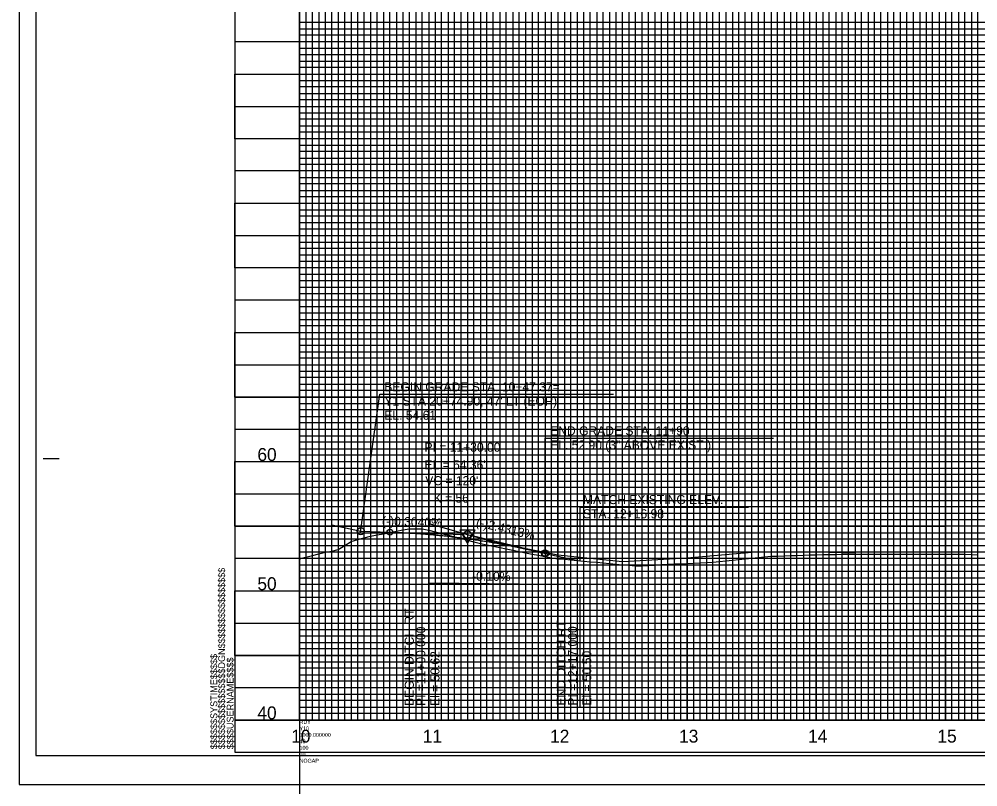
# Model space of a CAD drawing. Extents: x 2345490 to 2436403, y 465165 to 573888.
# Drawn here: x 2381550 to 2382292, y 532359 to 532954 of the extents above; entities that cross this region are included whole.
import ezdxf

# ---------------------------------------------------------------- set-up
doc = ezdxf.new("R2010")
doc.units = 0
for name, color, linetype in [('Old_Level_1', 7, 'Continuous'), ('Old_Level_18', 7, 'Continuous'), ('Old_Level_2', 7, 'Continuous'), ('Old_Level_3', 7, 'Continuous'), ('Old_Level_40', 7, 'Continuous'), ('Old_Level_41', 7, 'Continuous'), ('Old_Level_42', 7, 'Continuous'), ('Old_Level_43', 7, 'Continuous'), ('Old_Level_50', 7, 'Continuous'), ('Old_Level_51', 7, 'Continuous'), ('Old_Level_52', 7, 'Continuous'), ('Old_Level_57', 7, 'Continuous'), ('Old_Level_62', 7, 'Continuous'), ('Old_Level_63', 7, 'Continuous')]:
    doc.layers.add(name, color=color, linetype=linetype)

msp = doc.modelspace()

# ---------------------------------------------------------------- linework, layer by layer
at = {"layer": 'Old_Level_1'}
for points in [[(2381766.799, 532535.9075), (2381771.799, 532537.124), (2381776.799, 532538.34025), (2381781.799, 532539.65675), (2381786.799, 532540.84975), (2381791.799, 532541.76875), (2381796.799, 532543.1575), (2381801.799, 532546.145), (2381806.799, 532549.13275), (2381811.799, 532550.8695), (2381816.799, 532552.128), (2381821.799, 532553.4715), (2381826.799, 532554.3915), (2381831.799, 532555.2835), (2381836.799, 532556.27575), (2381841.799, 532557.2585), (2381846.799, 532558.14025), (2381851.799, 532558.90725), (2381856.799, 532559.102), (2381861.799, 532559.02975), (2381866.799, 532558.10175), (2381871.799, 532556.787), (2381876.799, 532555.472), (2381881.799, 532554.15725), (2381886.799, 532552.84225), (2381891.799, 532551.5275), (2381896.799, 532550.2095), (2381901.799, 532548.89425), (2381906.799, 532547.6065), (2381911.799, 532546.603), (2381916.799, 532545.59575), (2381921.799, 532544.58425), (2381926.799, 532543.57275), (2381931.799, 532542.5615), (2381936.799, 532541.56275), (2381941.799, 532540.554), (2381946.799, 532539.54525), (2381951.799, 532538.5365), (2381956.799, 532537.528), (2381961.799, 532536.51925), (2381966.799, 532535.87925), (2381971.799, 532535.4215), (2381976.799, 532534.964), (2381981.799, 532534.5065), (2381986.799, 532534.04875), (2381991.799, 532533.59125), (2381996.799, 532533.121), (2382001.799, 532532.6625), (2382006.799, 532532.20425), (2382011.799, 532531.74575), (2382016.799, 532531.28725), (2382021.799, 532530.82875), (2382026.799, 532530.425), (2382031.799, 532530.49175), (2382036.799, 532530.76025), (2382041.799, 532531.0285), (2382046.799, 532531.29675), (2382051.799, 532531.56525), (2382056.799, 532531.8335), (2382061.799, 532532.00825), (2382066.799, 532532.2765), (2382071.799, 532532.54475), (2382076.799, 532532.81325), (2382081.799, 532533.0815), (2382086.799, 532533.35), (2382091.799, 532533.7715), (2382096.799, 532534.27475), (2382101.799, 532534.778), (2382106.799, 532535.28125), (2382111.799, 532535.78425), (2382116.799, 532536.2875), (2382121.799, 532536.79075), (2382126.799, 532537.294), (2382131.799, 532537.76775), (2382136.799, 532537.97175), (2382141.799, 532538.1305), (2382146.799, 532538.28925), (2382151.799, 532538.448), (2382156.799, 532538.61975), (2382161.799, 532538.778), (2382166.799, 532538.93525), (2382171.799, 532539.089), (2382176.799, 532539.2225), (2382181.799, 532539.289), (2382186.799, 532539.35175), (2382191.799, 532539.41125), (2382196.799, 532539.467), (2382201.799, 532539.50625), (2382206.799, 532539.50325), (2382211.799, 532539.495), (2382216.799, 532539.48275), (2382221.799, 532539.467), (2382226.799, 532539.44825), (2382231.799, 532539.45125), (2382236.799, 532539.46675), (2382241.799, 532539.47825), (2382246.799, 532539.48625), (2382251.799, 532539.4905), (2382256.799, 532539.415), (2382261.799, 532539.396), (2382266.799, 532539.393)], [(2382266.799, 532539.393), (2382271.799, 532539.3855), (2382276.799, 532539.37325), (2382281.799, 532539.31625), (2382286.799, 532539.1095), (2382291.799, 532538.9875)]]:
    msp.add_lwpolyline(points, dxfattribs=at)
at = {"layer": 'Old_Level_18'}
msp.add_line((2381716.79875, 532386.04975), (2381716.79875, 532386.04975), dxfattribs=at)
msp.add_line((2381716.79875, 532386.04975), (2381716.79875, 532386.04975), dxfattribs=at)
msp.add_lwpolyline([(2383216.79875, 533436.04975), (2381716.79875, 533436.04975), (2381716.79875, 532386.04975), (2383216.79875, 532386.04975)], close=True, dxfattribs=at)
at = {"layer": 'Old_Level_2'}
for p, q in [((2381791.799, 532562.18325), (2381814.16925, 532557.15)), ((2381814.16925, 532557.15), (2381836.799, 532556.46225)), ((2381836.799, 532556.46225), (2381894.0505, 532554.72175)), ((2381956.799, 532540.05), (2381899.47125, 532553.9885)), ((2381956.799, 532540.05), (2381983.779, 532534.35025))]:
    msp.add_line(p, q, dxfattribs=at)
msp.add_lwpolyline([(2381902.72475, 532557.9225), (2381890.98225, 532557.908), (2381896.86575, 532547.78975)], close=True, dxfattribs=at)
for centre, radius in [((2381814.16925, 532557.15), 2.75), ((2381836.799, 532556.46225), 2.25), ((2381896.799, 532554.638), 2.75), ((2381896.799, 532554.638), 2.75), ((2381956.799, 532540.05), 2.75), ((2381956.799, 532540.05), 2.25)]:
    msp.add_circle(centre, radius, dxfattribs=at)
msp.add_spline([(2381836.799, 532556.46225), (2381839.199, 532556.384), (2381841.599, 532556.29575), (2381843.999, 532556.19725), (2381846.399, 532556.0885), (2381848.799, 532555.96975), (2381851.199, 532555.8405), (2381853.599, 532555.70125), (2381855.999, 532555.55175), (2381858.399, 532555.392), (2381860.799, 532555.222), (2381863.199, 532555.04175), (2381865.599, 532554.8515), (2381867.999, 532554.65075), (2381870.399, 532554.44), (2381872.799, 532554.219), (2381875.199, 532553.98775), (2381877.599, 532553.74625), (2381879.999, 532553.49475), (2381882.399, 532553.23275), (2381884.799, 532552.96075), (2381887.199, 532552.6785), (2381889.599, 532552.386), (2381891.999, 532552.08325), (2381894.399, 532551.77025), (2381896.799, 532551.447), (2381899.199, 532551.11375), (2381901.599, 532550.77025), (2381903.999, 532550.4165), (2381906.399, 532550.0525), (2381908.799, 532549.67825), (2381911.199, 532549.29375), (2381913.599, 532548.89925), (2381915.999, 532548.4945), (2381918.399, 532548.0795), (2381920.799, 532547.65425), (2381923.199, 532547.21875), (2381925.599, 532546.773), (2381927.999, 532546.31725), (2381930.399, 532545.851), (2381932.799, 532545.37475), (2381935.199, 532544.88825), (2381937.599, 532544.3915), (2381939.999, 532543.8845), (2381942.399, 532543.3675), (2381944.799, 532542.84), (2381947.199, 532542.3025), (2381949.599, 532541.75475), (2381951.999, 532541.19675), (2381954.399, 532540.6285), (2381956.799, 532540.05)], degree=3, dxfattribs=at)
at = {"layer": 'Old_Level_3'}
for p, q in [((2381814.03875, 532556.54975), (2381828.82525, 532663.237)), ((2381828.82525, 532663.237), (2382009.71375, 532663.237)), ((2381956.799, 532540.05), (2381956.799, 532629.18325)), ((2381956.799, 532629.18325), (2382133.76675, 532629.18325)), ((2381983.77875, 532575.91425), (2381983.77875, 532534.35025)), ((2381983.77875, 532575.91425), (2382114.25025, 532575.91425)), ((2381866.799, 532517.25), (2381983.799, 532516.05)), ((2381866.799, 532517.25), (2381866.799, 532420.84507)), ((2381983.799, 532516.05), (2381983.799, 532420.84507))]:
    msp.add_line(p, q, dxfattribs=at)
at = {"layer": 'Old_Level_40'}
msp.add_line((2381716.79875, 532386.04975), (2381716.79875, 532386.04975), dxfattribs=at)
msp.add_line((2381716.79875, 532386.04975), (2381716.79875, 532386.04975), dxfattribs=at)
msp.add_line((2381716.79875, 532386.04975), (2381716.79875, 532386.04975), dxfattribs=at)
msp.add_line((2381716.79875, 532386.04975), (2381716.79875, 532386.04975), dxfattribs=at)
at = {"layer": 'Old_Level_41'}
for p, q in [((2381568.29875, 532613.54975), (2381580.79875, 532613.54975)), ((2383216.79875, 532411.04975), (2381716.79875, 532411.04975))]:
    msp.add_line(p, q, dxfattribs=at)
for points in [[(2381716.79875, 533436.04975), (2381766.79875, 533436.04975), (2381766.79875, 532411.04975), (2381816.79875, 532411.04975), (2381816.79875, 533436.04975), (2381866.79875, 533436.04975), (2381866.79875, 532411.04975), (2381916.79875, 532411.04975), (2381916.79875, 533436.04975), (2381966.79875, 533436.04975), (2381966.79875, 532411.04975), (2382016.79875, 532411.04975), (2382016.79875, 533436.04975), (2382066.79875, 533436.04975), (2382066.79875, 532411.04975), (2382116.79875, 532411.04975), (2382116.79875, 533436.04975), (2382166.79875, 533436.04975), (2382166.79875, 532411.04975), (2382216.79875, 532411.04975), (2382216.79875, 533436.04975), (2382266.79875, 533436.04975), (2382266.79875, 532411.04975), (2382316.79875, 532411.04975)], [(2381791.79875, 532411.04975), (2381791.79875, 533436.04975), (2381841.79875, 533436.04975), (2381841.79875, 532411.04975), (2381891.79875, 532411.04975), (2381891.79875, 533436.04975), (2381941.79875, 533436.04975), (2381941.79875, 532411.04975), (2381991.79875, 532411.04975), (2381991.79875, 533436.04975), (2382041.79875, 533436.04975), (2382041.79875, 532411.04975), (2382091.79875, 532411.04975), (2382091.79875, 533436.04975), (2382141.79875, 533436.04975), (2382141.79875, 532411.04975), (2382191.79875, 532411.04975), (2382191.79875, 533436.04975), (2382241.79875, 533436.04975), (2382241.79875, 532411.04975), (2382291.79875, 532411.04975), (2382291.79875, 533436.04975), (2382341.79875, 533436.04975)], [(2383216.79875, 532936.04975), (2381716.79875, 532936.04975), (2381716.79875, 532886.04975), (2383216.79875, 532886.04975)], [(2383216.79875, 532836.04975), (2381716.79875, 532836.04975), (2381716.79875, 532786.04975), (2383216.79875, 532786.04975)], [(2383216.79875, 532761.04975), (2381716.79875, 532761.04975), (2381716.79875, 532811.04975), (2383216.79875, 532811.04975)], [(2383216.79875, 532736.04975), (2381716.79875, 532736.04975), (2381716.79875, 532686.04975), (2383216.79875, 532686.04975)], [(2383216.79875, 532661.04975), (2381716.79875, 532661.04975), (2381716.79875, 532711.04975), (2383216.79875, 532711.04975)], [(2383216.79875, 532636.04975), (2381716.79875, 532636.04975), (2381716.79875, 532586.04975), (2383216.79875, 532586.04975)], [(2383216.79875, 532536.04975), (2381716.79875, 532536.04975), (2381716.79875, 532486.04975), (2383216.79875, 532486.04975)], [(2383216.79875, 532461.04975), (2381716.79875, 532461.04975), (2381716.79875, 532511.04975), (2383216.79875, 532511.04975)], [(2383216.79875, 532436.04975), (2381716.79875, 532436.04975)], [(2381754.29875, 532386.04975), (2381754.29875, 532386.04975)]]:
    msp.add_lwpolyline(points, dxfattribs=at)
at = {"layer": 'Old_Level_42'}
for points in [[(2383216.79875, 532861.04975), (2381716.79875, 532861.04975), (2381716.79875, 532911.04975), (2383216.79875, 532911.04975)], [(2383216.79875, 532561.04975), (2381716.79875, 532561.04975), (2381716.79875, 532611.04975), (2383216.79875, 532611.04975)]]:
    msp.add_lwpolyline(points, dxfattribs=at)
at = {"layer": 'Old_Level_43'}
for points in [[(2381771.79875, 533436.04975), (2381771.79875, 532411.04975), (2381776.79875, 532411.04975), (2381776.79875, 533436.04975)], [(2381781.79875, 533436.04975), (2381781.79875, 532411.04975), (2381786.79875, 532411.04975), (2381786.79875, 533436.04975)], [(2381796.79875, 533436.04975), (2381796.79875, 532411.04975), (2381801.79875, 532411.04975), (2381801.79875, 533436.04975)], [(2381806.79875, 533436.04975), (2381806.79875, 532411.04975), (2381811.79875, 532411.04975), (2381811.79875, 533436.04975)], [(2381821.79875, 533436.04975), (2381821.79875, 532411.04975), (2381826.79875, 532411.04975), (2381826.79875, 533436.04975)], [(2381831.79875, 533436.04975), (2381831.79875, 532411.04975), (2381836.79875, 532411.04975), (2381836.79875, 533436.04975)], [(2381846.79875, 533436.04975), (2381846.79875, 532411.04975), (2381851.79875, 532411.04975), (2381851.79875, 533436.04975)], [(2381856.79875, 533436.04975), (2381856.79875, 532411.04975), (2381861.79875, 532411.04975), (2381861.79875, 533436.04975)], [(2381871.79875, 533436.04975), (2381871.79875, 532411.04975), (2381876.79875, 532411.04975), (2381876.79875, 533436.04975)], [(2381881.79875, 533436.04975), (2381881.79875, 532411.04975), (2381886.79875, 532411.04975), (2381886.79875, 533436.04975)], [(2381896.79875, 533436.04975), (2381896.79875, 532411.04975), (2381901.79875, 532411.04975), (2381901.79875, 533436.04975)], [(2381906.79875, 533436.04975), (2381906.79875, 532411.04975), (2381911.79875, 532411.04975), (2381911.79875, 533436.04975)], [(2381921.79875, 533436.04975), (2381921.79875, 532411.04975), (2381926.79875, 532411.04975), (2381926.79875, 533436.04975)], [(2381931.79875, 532411.04975), (2381936.79875, 532411.04975), (2381936.79875, 533436.04975)], [(2381931.79875, 533436.04975), (2381931.79875, 532411.04975)], [(2381946.79875, 533436.04975), (2381946.79875, 532411.04975), (2381951.79875, 532411.04975), (2381951.79875, 533436.04975)], [(2381956.79875, 533436.04975), (2381956.79875, 532411.04975), (2381961.79875, 532411.04975), (2381961.79875, 533436.04975)], [(2381971.79875, 533436.04975), (2381971.79875, 532411.04975), (2381976.79875, 532411.04975), (2381976.79875, 533436.04975)], [(2381981.79875, 533436.04975), (2381981.79875, 532411.04975), (2381986.79875, 532411.04975), (2381986.79875, 533436.04975)], [(2381996.79875, 533436.04975), (2381996.79875, 532411.04975), (2382001.79875, 532411.04975), (2382001.79875, 533436.04975)], [(2382006.79875, 533436.04975), (2382006.79875, 532411.04975), (2382011.79875, 532411.04975), (2382011.79875, 533436.04975)], [(2382021.79875, 533436.04975), (2382021.79875, 532411.04975), (2382026.79875, 532411.04975), (2382026.79875, 533436.04975)], [(2382031.79875, 533436.04975), (2382031.79875, 532411.04975), (2382036.79875, 532411.04975), (2382036.79875, 533436.04975)], [(2382046.79875, 533436.04975), (2382046.79875, 532411.04975), (2382051.79875, 532411.04975), (2382051.79875, 533436.04975)], [(2382056.79875, 533436.04975), (2382056.79875, 532411.04975), (2382061.79875, 532411.04975), (2382061.79875, 533436.04975)], [(2382071.79875, 533436.04975), (2382071.79875, 532411.04975), (2382076.79875, 532411.04975), (2382076.79875, 533436.04975)], [(2382081.79875, 533436.04975), (2382081.79875, 532411.04975), (2382086.79875, 532411.04975), (2382086.79875, 533436.04975)], [(2382096.79875, 533436.04975), (2382096.79875, 532411.04975), (2382111.79875, 532411.04975), (2382111.79875, 533436.04975)], [(2382101.79875, 533436.04975), (2382101.79875, 532411.04975), (2382106.79875, 532411.04975), (2382106.79875, 533436.04975)], [(2382101.79875, 533435.44975), (2382101.79875, 532411.04975), (2382106.79875, 532411.04975), (2382106.79875, 533435.44975)], [(2382121.79875, 533436.04975), (2382121.79875, 532411.04975), (2382126.79875, 532411.04975), (2382126.79875, 533436.04975)], [(2382131.79875, 533436.04975), (2382131.79875, 532411.04975), (2382136.79875, 532411.04975), (2382136.79875, 533436.04975)], [(2382146.79875, 533436.04975), (2382146.79875, 532411.04975), (2382151.79875, 532411.04975), (2382151.79875, 533436.04975)], [(2382156.79875, 533436.04975), (2382156.79875, 532411.04975), (2382161.79875, 532411.04975), (2382161.79875, 533436.04975)], [(2382171.79875, 533436.04975), (2382171.79875, 532411.04975), (2382176.79875, 532411.04975), (2382176.79875, 533436.04975)], [(2382181.79875, 533436.04975), (2382181.79875, 532411.04975), (2382186.79875, 532411.04975), (2382186.79875, 533436.04975)], [(2382196.79875, 533436.04975), (2382196.79875, 532411.04975), (2382201.79875, 532411.04975), (2382201.79875, 533436.04975)], [(2382206.79875, 533436.04975), (2382206.79875, 532411.04975), (2382211.79875, 532411.04975), (2382211.79875, 533436.04975)], [(2382221.79875, 533436.04975), (2382221.79875, 532411.04975), (2382226.79875, 532411.04975), (2382226.79875, 533436.04975)], [(2382231.79875, 533436.04975), (2382231.79875, 532411.04975), (2382236.79875, 532411.04975), (2382236.79875, 533436.04975)], [(2382246.79875, 533436.04975), (2382246.79875, 532411.04975)], [(2382251.79875, 533436.04975), (2382251.79875, 532411.04975), (2382256.79875, 532411.04975), (2382256.79875, 533436.04975), (2382261.79875, 533436.04975), (2382261.79875, 532411.04975), (2382271.79875, 532411.04975), (2382271.79875, 533436.04975), (2382276.79875, 533436.04975), (2382276.79875, 532411.04975), (2382281.79875, 532411.04975), (2382281.79875, 533436.04975), (2382286.79875, 533436.04975), (2382286.79875, 532411.04975)], [(2383166.79875, 532951.04975), (2381766.79875, 532951.04975), (2381766.79875, 532946.04975), (2383166.79875, 532946.04975)], [(2383166.79875, 532941.04975), (2381766.79875, 532941.04975), (2381766.79875, 532931.04975), (2383166.79875, 532931.04975)], [(2383166.79875, 532926.04975), (2381766.79875, 532926.04975), (2381766.79875, 532921.04975), (2383166.79875, 532921.04975)], [(2383166.79875, 532916.04975), (2381766.79875, 532916.04975)], [(2381766.79875, 532906.04975), (2383166.79875, 532906.04975)], [(2383166.79875, 532901.04975), (2381766.79875, 532901.04975), (2381766.79875, 532896.04975), (2383166.79875, 532896.04975)], [(2383166.79875, 532891.04975), (2381766.79875, 532891.04975), (2381766.79875, 532881.04975), (2383166.79875, 532881.04975)], [(2383166.79875, 532876.04975), (2381766.79875, 532876.04975), (2381766.79875, 532871.04975), (2383166.79875, 532871.04975)], [(2383166.79875, 532866.04975), (2381766.79875, 532866.04975), (2381766.79875, 532856.04975), (2383166.79875, 532856.04975)], [(2383166.79875, 532851.04975), (2381766.79875, 532851.04975), (2381766.79875, 532846.04975), (2383166.79875, 532846.04975)], [(2383166.79875, 532841.04975), (2381766.79875, 532841.04975), (2381766.79875, 532831.04975), (2383166.79875, 532831.04975)], [(2383166.79875, 532826.04975), (2381766.79875, 532826.04975), (2381766.79875, 532821.04975), (2383166.79875, 532821.04975)], [(2383166.79875, 532816.04975), (2381766.79875, 532816.04975), (2381766.79875, 532806.04975), (2383166.79875, 532806.04975)], [(2383166.79875, 532801.04975), (2381766.79875, 532801.04975), (2381766.79875, 532796.04975), (2383166.79875, 532796.04975)], [(2383166.79875, 532791.04975), (2381766.79875, 532791.04975), (2381766.79875, 532781.04975), (2383166.79875, 532781.04975)], [(2383166.79875, 532776.04975), (2381766.79875, 532776.04975), (2381766.79875, 532771.04975), (2383166.79875, 532771.04975)], [(2383166.79875, 532766.04975), (2381766.79875, 532766.04975), (2381766.79875, 532756.04975), (2383166.79875, 532756.04975)], [(2383166.79875, 532751.04975), (2381766.79875, 532751.04975), (2381766.79875, 532746.04975), (2383166.79875, 532746.04975)], [(2383166.79875, 532741.04975), (2381766.79875, 532741.04975), (2381766.79875, 532731.04975), (2383166.79875, 532731.04975)], [(2383166.79875, 532726.04975), (2381766.79875, 532726.04975), (2381766.79875, 532721.04975), (2383166.79875, 532721.04975)], [(2383166.79875, 532716.04975), (2381766.79875, 532716.04975), (2381766.79875, 532706.04975), (2383166.79875, 532706.04975)], [(2383166.79875, 532701.04975), (2381766.79875, 532701.04975), (2381766.79875, 532696.04975), (2383166.79875, 532696.04975)], [(2383166.79875, 532691.04975), (2381766.79875, 532691.04975), (2381766.79875, 532681.04975), (2383166.79875, 532681.04975)], [(2383166.79875, 532676.04975), (2381766.79875, 532676.04975), (2381766.79875, 532671.04975), (2383166.79875, 532671.04975)], [(2383166.79875, 532666.04975), (2381766.79875, 532666.04975), (2381766.79875, 532656.04975), (2383166.79875, 532656.04975)], [(2383166.79875, 532651.04975), (2381766.79875, 532651.04975), (2381766.79875, 532646.04975), (2383166.79875, 532646.04975)], [(2383166.79875, 532641.04975), (2381766.79875, 532641.04975), (2381766.79875, 532631.04975), (2383166.79875, 532631.04975)], [(2383166.79875, 532626.04975), (2381766.79875, 532626.04975), (2381766.79875, 532621.04975), (2383166.79875, 532621.04975)], [(2383166.79875, 532616.04975), (2381766.79875, 532616.04975)], [(2381766.79875, 532606.04975), (2383166.79875, 532606.04975)], [(2383166.79875, 532601.04975), (2381766.79875, 532601.04975), (2381766.79875, 532596.04975), (2383166.79875, 532596.04975)], [(2383166.79875, 532591.04975), (2381766.79875, 532591.04975)], [(2381766.79875, 532581.04975), (2383166.79875, 532581.04975)], [(2383166.79875, 532576.04975), (2381766.79875, 532576.04975), (2381766.79875, 532571.04975), (2383166.79875, 532571.04975)], [(2383166.79875, 532566.04975), (2381766.79875, 532566.04975), (2381766.79875, 532556.04975), (2383166.79875, 532556.04975)], [(2383166.79875, 532551.04975), (2381766.79875, 532551.04975), (2381766.79875, 532546.04975), (2383166.79875, 532546.04975)], [(2383166.79875, 532541.04975), (2381766.79875, 532541.04975), (2381766.79875, 532531.04975), (2383166.79875, 532531.04975)], [(2383166.79875, 532526.04975), (2381766.79875, 532526.04975), (2381766.79875, 532521.04975), (2383166.79875, 532521.04975)], [(2383166.79875, 532516.04975), (2381766.79875, 532516.04975), (2381766.79875, 532506.04975), (2383166.79875, 532506.04975)], [(2383166.79875, 532501.04975), (2381766.79875, 532501.04975), (2381766.79875, 532496.04975), (2383166.79875, 532496.04975)], [(2383166.79875, 532491.04975), (2381766.79875, 532491.04975), (2381766.79875, 532481.04975), (2383166.79875, 532481.04975)], [(2383166.79875, 532476.04975), (2381766.79875, 532476.04975), (2381766.79875, 532471.04975), (2383166.79875, 532471.04975)], [(2383166.79875, 532466.04975), (2381766.79875, 532466.04975), (2381766.79875, 532456.04975), (2383166.79875, 532456.04975)], [(2383166.79875, 532451.04975), (2381766.79875, 532451.04975), (2381766.79875, 532446.04975), (2383166.79875, 532446.04975)], [(2383166.79875, 532441.04975), (2381766.79875, 532441.04975), (2381766.79875, 532431.04975), (2383166.79875, 532431.04975)], [(2383166.79875, 532426.04975), (2381766.79875, 532426.04975), (2381766.79875, 532421.04975), (2383166.79875, 532421.04975)], [(2383166.79875, 532416.04975), (2381766.79875, 532416.04975)]]:
    msp.add_lwpolyline(points, dxfattribs=at)
at = {"layer": 'Old_Level_50'}
msp.add_line((2381549.79875, 532361.04975), (2381549.79875, 532361.04975), dxfattribs=at)
msp.add_lwpolyline([(2383229.29875, 533438.59975), (2381562.79875, 533438.59975), (2381562.79875, 532383.49975), (2383229.29875, 532383.49975)], close=True, dxfattribs=at)
at = {"layer": 'Old_Level_51'}
msp.add_lwpolyline([(2383233.79875, 533461.04975), (2381549.79875, 533461.04975), (2381549.79875, 532361.04975), (2383233.79875, 532361.04975)], close=True, dxfattribs=at)
at = {"layer": 'Old_Level_52'}
msp.add_line((2381562.79875, 532383.49975), (2381562.79875, 532383.49975), dxfattribs=at)
at = {"layer": 'Old_Level_57'}
for p, q in [((2381716.79925, 532661.05025), (2382266.79875, 532661.05025)), ((2381766.79875, 532411.05025), (2381766.79875, 532661.05025)), ((2381866.79875, 532411.05025), (2381866.79875, 532661.05025)), ((2381966.79875, 532411.05025), (2381966.79875, 532661.05025)), ((2382066.79875, 532411.05025), (2382066.79875, 532661.05025)), ((2382166.79875, 532411.05025), (2382166.79875, 532661.05025)), ((2382266.79875, 532411.05025), (2382266.79875, 532661.05025)), ((2381716.79925, 532611.05025), (2382266.79875, 532611.05025)), ((2381716.79925, 532561.05025), (2382266.79875, 532561.05025)), ((2381716.79925, 532511.05025), (2382266.79875, 532511.05025)), ((2381716.799, 532461.05025), (2382266.79875, 532461.05025)), ((2381716.79925, 532411.05025), (2382266.79875, 532411.05025))]:
    msp.add_line(p, q, dxfattribs=at)
at = {"layer": 'Old_Level_63'}
for q in [(2381766.79875, 534911.04975), (2382198.83425, 532411.04975), (2381766.79875, 529911.04975)]:
    msp.add_line((2381766.79875, 532411.04975), q, dxfattribs=at)
msp.add_lwpolyline([(2381866.799, 532563.05), (2381916.799, 532549.05), (2381966.799, 532538.95), (2382016.799, 532533.85), (2382066.799, 532536.65), (2382116.799, 532540.85), (2382166.799, 532541.35), (2382196.799, 532540.55)], dxfattribs=at)

# ---------------------------------------------------------------- texts
at = {"layer": 'Old_Level_2'}
for s, height, p in [('BEGIN GRADE STA. 10+47.37=', 7.0000005, (2381832.41675, 532665.46)), ("Y1 STA 20+74.90, 47' LT (EOP)", 7.0000005, (2381832.41675, 532654.46)), ('EL. 54.61', 7.000001, (2381832.41675, 532643.46)), ('END GRADE STA. 11+90', 7.0000005, (2381960.788, 532631.4475)), ('PI = 11+30.00', 7.0000005, (2381863.519, 532618.7195)), ('EL. 52.90 (3" ABOVE EXIST.)', 7.0000005, (2381960.788, 532620.4475)), ("EL = 54.36'", 7.0000005, (2381863.5195, 532605.171)), ("VC = 120'", 7.000001, (2381864.124, 532592.79775)), ('K = 56', 7.000001, (2381870.573, 532579.2735)), ('MATCH EXISTING ELEV.', 7.0000005, (2381986.16675, 532578.17825)), ('STA. 12+16.98', 7.0000005, (2381986.16675, 532567.17825))]:
    msp.add_text(s, height=height, dxfattribs=at).set_placement(p)
for s, rotation, p in [('(-)0.3040%', 358.25869167, (2381830.54325, 532561.69675)), ('(-)2.4313%', 346.33466389, (2381902.9915, 532561.28375))]:
    msp.add_text(s, height=7.000001, rotation=rotation, dxfattribs=at).set_placement(p)
at = {"layer": 'Old_Level_3'}
for s, height, rotation, p in [('-0.10%', 7, 359.4124, (2381900.3665, 532518.971)), ('BEGIN DITCH RT', 7.0000005, 90, (2381855.24905, 532421.93915)), ('PI =11+00.000', 7.0000005, 90, (2381864.12295, 532421.93915)), ('END DITCH RT', 7.0000005, 90, (2381972.75967, 532422.18661)), ('PI =12+17.000', 7.0000005, 90, (2381981.63358, 532422.18661)), ('El = 50.62', 7.000001, 90, (2381875.12295, 532421.93915)), ('El = 50.50', 7.000001, 90, (2381992.63358, 532422.18661))]:
    msp.add_text(s, height=height, rotation=rotation, dxfattribs=at).set_placement(p)
at = {"layer": 'Old_Level_41'}
for s, p in [('$$$$$$$$$$$$$$$$DGN$$$$$$$$$$$$$$$$', (2381709.14875, 532388.41225)), ('$$$$$$SYSTIME$$$$$', (2381703.09875, 532388.41225)), ('$$$$USERNAME$$$$', (2381715.72375, 532388.42475))]:
    msp.add_text(s, height=5.25, rotation=90, dxfattribs=at).set_placement(p)
at = {"layer": 'Old_Level_62'}
for s, p in [('60', (2381734.1855, 532611.55)), ('50', (2381734.1855, 532511.55)), ('40', (2381734.1855, 532411.55)), ('10', (2381760.3825, 532393.55)), ('11', (2381862.222, 532393.55)), ('12', (2381960.77025, 532393.55)), ('13', (2382060.605, 532393.55)), ('14', (2382160.4475, 532393.55)), ('15', (2382260.54, 532393.55))]:
    msp.add_text(s, height=10.000001, dxfattribs=at).set_placement(p)
at = {"layer": 'Old_Level_63'}
for s, p in [('RDY', (2381766.79875, 532408.04975)), ('Y10', (2381766.79875, 532403.04975)), ('1000.000000', (2381766.79875, 532398.04975)), ('40', (2381766.79875, 532393.04975)), ('100', (2381766.79875, 532388.04975)), ('10', (2381766.79875, 532383.04975)), ('NOGAP', (2381766.79875, 532378.04975))]:
    msp.add_text(s, height=3, dxfattribs=at).set_placement(p)

doc.saveas('drawing.dxf')
